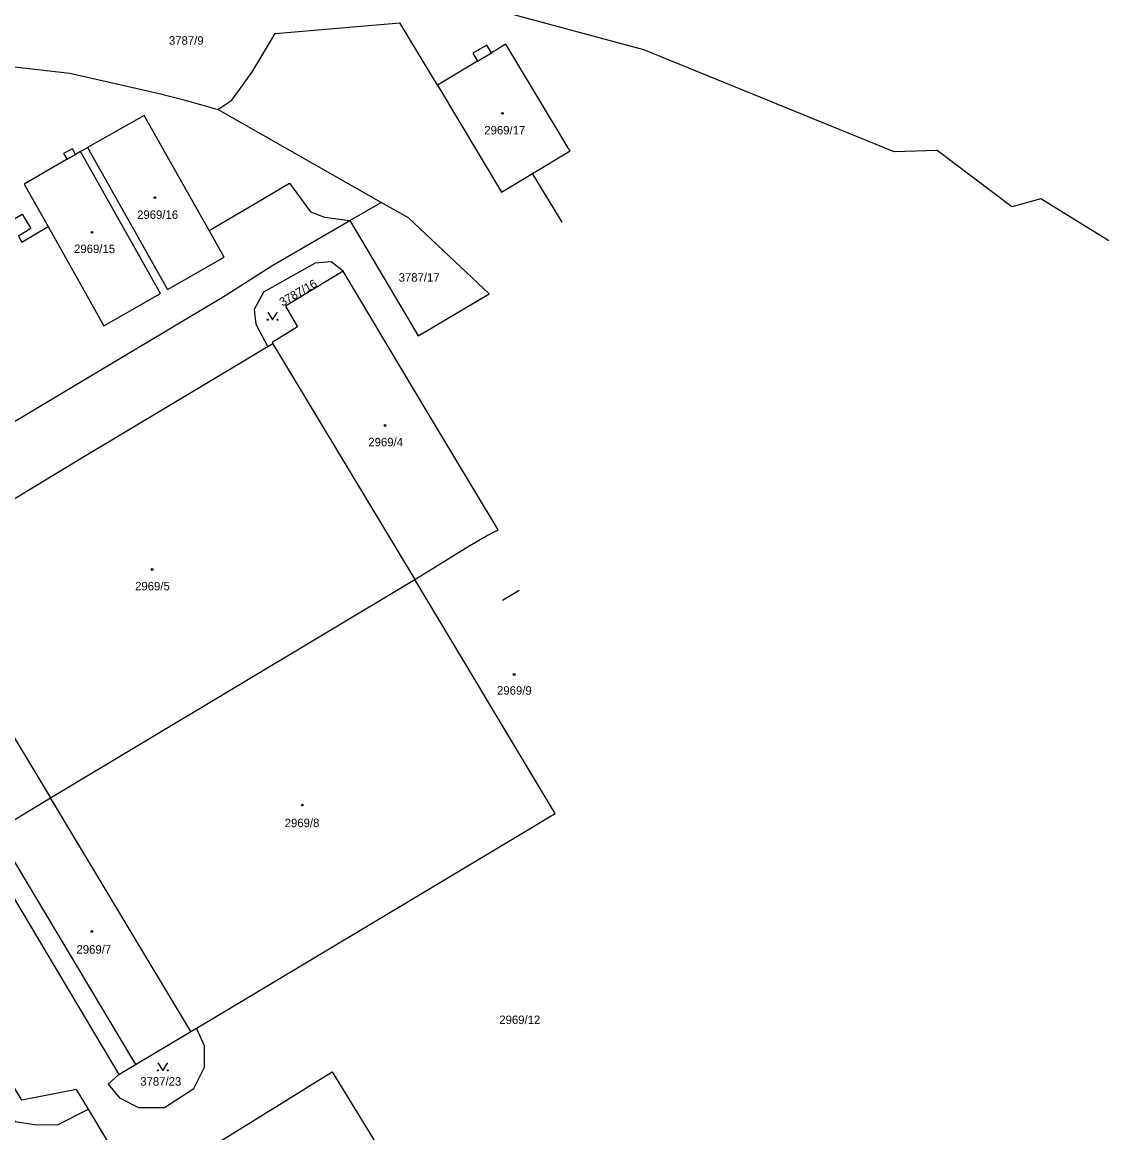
# Model space of a CAD drawing. Extents: x -527335 to -526256, y -1079142 to -1077836.
# Drawn here: x -526473.7 to -526255.8, y -1078664.8 to -1078442 of the extents above; entities that cross this region are included whole.
import ezdxf

# ---------------------------------------------------------------- set-up
doc = ezdxf.new("R2010")
doc.units = 0
for name, color, linetype in [('Hranice parcel', 7, 'Continuous'), ('Parcelní čísla', 7, 'Continuous'), ('Vnitřní kresba', 7, 'Continuous'), ('Značky budov', 7, 'Continuous'), ('Značky kultur', 7, 'Continuous')]:
    doc.layers.add(name, color=color, linetype=linetype)

msp = doc.modelspace()

# ---------------------------------------------------------------- linework, layer by layer
at = {"layer": 'Hranice parcel'}
for p, q in [((-526390.49, -1078454.67), (-526398.01, -1078442.14)), ((-526401.75, -1078478.18), (-526434.53, -1078459.51)), ((-526462.04, -1078467.96), (-526460.66, -1078467.18)), ((-526365.44, -1078482.13), (-526371.4, -1078472.38)), ((-526408.05, -1078481.83), (-526401.75, -1078478.18)), ((-526423.48, -1078506.53), (-526424.51, -1078507.15)), ((-526423.48, -1078506.53), (-526395.01, -1078553.82)), ((-526496.51, -1078550.45), (-526468.06, -1078597.62)), ((-526468.06, -1078597.62), (-526395.01, -1078553.82)), ((-526366.88, -1078600.75), (-526395.01, -1078553.82)), ((-526439.96, -1078644.47), (-526468.06, -1078597.62)), ((-526482.37, -1078606.2), (-526454.36, -1078653.08)), ((-526439.96, -1078644.47), (-526438.79, -1078643.77)), ((-526456.6, -1078666.52), (-526460.45, -1078660.06))]:
    msp.add_line(p, q, dxfattribs=at)
for points in [[(-526255.84, -1078485.88), (-526269.44, -1078477.46), (-526275.29, -1078479.08), (-526290.24, -1078467.75), (-526298.87, -1078468), (-526349.1, -1078447.58), (-526381.09, -1078438.93), (-526412.01, -1078434.75), (-526470.91, -1078435.12), (-526515.41, -1078439.88), (-526541.88, -1078447.21), (-526576.22, -1078459.13), (-526589.61, -1078459.9), (-526628.8, -1078481.46), (-526632.26, -1078483.8)], [(-526434.53, -1078459.51), (-526431.72, -1078457.68), (-526427.71, -1078452.11), (-526423.05, -1078444.29), (-526398.01, -1078442.14)], [(-526364.05, -1078467.53), (-526376.73, -1078446.46), (-526379.64, -1078448.2), (-526380.59, -1078446.61), (-526383.37, -1078448.26), (-526382.42, -1078449.85), (-526390.49, -1078454.67)], [(-526561.62, -1078458.12), (-526556.1, -1078456.24), (-526538.7, -1078451.42), (-526526.69, -1078449.93), (-526506.02, -1078449.43), (-526490.82, -1078449.67), (-526475.86, -1078450.92), (-526464.21, -1078452.25), (-526446.58, -1078456.25), (-526440.77, -1078457.7), (-526434.53, -1078459.51)], [(-526390.49, -1078454.67), (-526377.62, -1078476.11), (-526371.4, -1078472.38)], [(-526436.22, -1078483.83), (-526449.28, -1078460.76), (-526460.66, -1078467.18)], [(-526462.04, -1078467.96), (-526463.04, -1078468.53), (-526463.67, -1078467.44), (-526465.44, -1078468.33), (-526464.75, -1078469.52), (-526473.35, -1078474.48), (-526468.56, -1078483.02)], [(-526468.56, -1078483.02), (-526457.39, -1078502.95), (-526445.99, -1078496.44), (-526462.04, -1078467.96)], [(-526460.66, -1078467.18), (-526444.61, -1078495.62), (-526433.22, -1078489.14), (-526436.22, -1078483.83)], [(-526371.4, -1078472.38), (-526363.86, -1078467.85), (-526364.05, -1078467.53)], [(-526436.22, -1078483.83), (-526427.06, -1078478.38), (-526420.17, -1078474.28), (-526415.95, -1078480.07), (-526413.09, -1078481.16), (-526408.05, -1078481.83)], [(-526489.6, -1078482.49), (-526479.94, -1078477.61), (-526477.03, -1078482.5), (-526473.76, -1078480.51), (-526472, -1078483.43), (-526474.52, -1078484.96), (-526473.8, -1078486.15), (-526468.56, -1078483.02)], [(-526380.11, -1078496.53), (-526396.29, -1078481.29), (-526401.75, -1078478.18)], [(-526523.77, -1078550.34), (-526505.2, -1078540.05), (-526486.35, -1078528.69), (-526465.12, -1078516.06), (-526433.26, -1078496.98), (-526423.51, -1078490.78), (-526408.05, -1078481.83)], [(-526408.05, -1078481.83), (-526395.67, -1078502.64), (-526394.31, -1078504.92)], [(-526409.39, -1078491.99), (-526411.77, -1078490.06), (-526414.97, -1078490.36), (-526425.38, -1078496.15), (-526427.22, -1078499.62), (-526426.89, -1078502.56), (-526424.57, -1078507.03), (-526424.51, -1078507.15)], [(-526409.39, -1078491.99), (-526420.96, -1078499), (-526418.53, -1078503.14), (-526423.65, -1078506.24), (-526423.48, -1078506.53)], [(-526380.64, -1078545.01), (-526378.32, -1078543.81), (-526392.13, -1078520.81), (-526409.39, -1078491.99)], [(-526394.31, -1078504.92), (-526392.74, -1078503.99), (-526380.11, -1078496.53)], [(-526424.51, -1078507.15), (-526424.73, -1078507.28), (-526428.61, -1078509.6), (-526461.89, -1078529.55), (-526491.29, -1078547.29), (-526495.23, -1078549.67), (-526495.49, -1078549.83)], [(-526395.01, -1078553.82), (-526383.96, -1078547.01), (-526380.64, -1078545.01)], [(-526507.8, -1078581.45), (-526513.68, -1078580.21), (-526515.08, -1078581.28), (-526517.57, -1078586.65), (-526517.96, -1078593.09), (-526516.49, -1078609.57), (-526490.68, -1078647.6), (-526486.57, -1078649.86), (-526481.38, -1078657.09), (-526475.07, -1078662.48), (-526471.37, -1078663.11), (-526466.68, -1078663.19), (-526460.45, -1078660.06)], [(-526460.45, -1078660.06), (-526462.86, -1078656.06), (-526473.81, -1078658.24), (-526496.71, -1078620.35), (-526488.48, -1078613.73), (-526499.93, -1078594.58), (-526505.29, -1078597.66), (-526511.58, -1078587.21), (-526506.29, -1078583.97), (-526507.8, -1078581.45)], [(-526482.37, -1078606.2), (-526479.05, -1078604.2), (-526468.06, -1078597.62)], [(-526438.79, -1078643.77), (-526435.21, -1078641.63), (-526371.52, -1078603.53), (-526368.01, -1078601.43), (-526366.88, -1078600.75)], [(-526454.36, -1078653.08), (-526456.53, -1078655), (-526454.22, -1078657.74), (-526450.45, -1078659.69), (-526445.2, -1078659.72), (-526439.34, -1078655.88), (-526437.19, -1078651.61), (-526437.18, -1078647.33), (-526438.79, -1078643.77)], [(-526454.36, -1078653.08), (-526451.02, -1078651.08), (-526439.96, -1078644.47)], [(-526443.9, -1078676.11), (-526439.15, -1078673.33), (-526440.79, -1078670.66), (-526411.59, -1078652.55), (-526399.61, -1078672.09), (-526428.92, -1078690.08), (-526430.5, -1078687.59), (-526435.4, -1078690.65)]]:
    msp.add_lwpolyline(points, dxfattribs=at)
at = {"layer": 'Vnitřní kresba'}
for p, q in [((-526382.42, -1078449.85), (-526379.64, -1078448.2)), ((-526464.75, -1078469.52), (-526463.04, -1078468.53)), ((-526377.42, -1078557.96), (-526374.1, -1078555.96)), ((-526479.05, -1078604.2), (-526451.02, -1078651.08))]:
    msp.add_line(p, q, dxfattribs=at)
at = {"layer": 'Značky budov'}
for centre in [(-526377.45, -1078460.31), (-526447.14, -1078477.22), (-526459.75, -1078484.16), (-526400.99, -1078522.92), (-526447.67, -1078551.79), (-526375.09, -1078572.85), (-526417.57, -1078599.05), (-526459.77, -1078624.4)]:
    msp.add_circle(centre, 0.175, dxfattribs=at)
at = {"layer": 'Značky kultur'}
for points in [[(-526424.52, -1078500.2), (-526423.52, -1078501.7), (-526422.52, -1078500.2)], [(-526446.55, -1078650.76), (-526445.55, -1078652.26), (-526444.55, -1078650.76)]]:
    msp.add_lwpolyline(points, dxfattribs=at)
for centre in [(-526424.52, -1078501.7), (-526422.52, -1078501.7), (-526446.55, -1078652.26), (-526444.55, -1078652.26)]:
    msp.add_circle(centre, 0.1, dxfattribs=at)

# ---------------------------------------------------------------- texts
at = {"layer": 'Parcelní čísla'}
for s, p in [('3787/9', (-526444.32, -1078446.54)), ('2969/17', (-526381.08, -1078464.54)), ('2969/16', (-526450.7, -1078481.48)), ('2969/15', (-526463.34, -1078488.33)), ('3787/17', (-526398.26, -1078494.07)), ('2969/4', (-526404.34, -1078527.09)), ('2969/5', (-526451.1, -1078555.98)), ('2969/9', (-526378.52, -1078576.9)), ('2969/8', (-526421.11, -1078603.47)), ('2969/7', (-526462.86, -1078628.84)), ('2969/12', (-526378.07, -1078642.96)), ('3787/23', (-526450.07, -1078655.31))]:
    msp.add_text(s, height=1.7, dxfattribs=at).set_placement(p)
msp.add_text('3787/16', height=1.7, rotation=30, dxfattribs=at).set_placement((-526421.56, -1078499.06))

doc.saveas('drawing.dxf')
